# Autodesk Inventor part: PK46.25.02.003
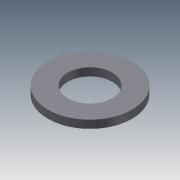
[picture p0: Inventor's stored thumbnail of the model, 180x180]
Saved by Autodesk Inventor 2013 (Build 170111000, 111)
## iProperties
Created: 2005-04
Part Number: PK46.25.02.003
Material: Steel, Mild
Document SubType Name: Modeling
Designer: salex
Manufacturer: Standard
Standards Organization: Custom
Density: 7.86 g/cm^3
Mass: 2054.45 g
Surface Area: 457.416 cm^2
Volume: 261.381 cm^3
Author: salex
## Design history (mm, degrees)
sketch "Эскиз1"
  geometry: C1 r 45 at (0, 0); C2 r 85 at (0, 0)
  constraints: 2 centre point, 1 coincident
  dimensions: "d0" = 170 diameter of C2; "d1" = 90 diameter of C1
extrude "Выдавливание1" new body sketch "Эскиз1" distance "d2" = 16; taper "d3" = 0 deg
body "Solid1"
